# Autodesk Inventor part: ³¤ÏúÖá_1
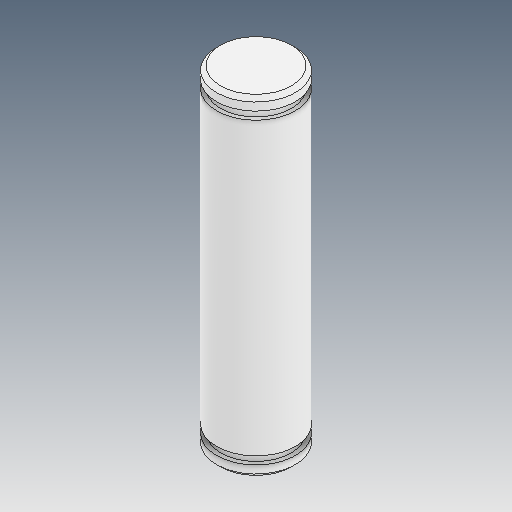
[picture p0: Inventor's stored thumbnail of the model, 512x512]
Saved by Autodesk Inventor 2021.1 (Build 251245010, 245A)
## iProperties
Created: 2021-05
Part Number: ³¤ÏúÖá_1
Material: Ogólny
Document SubType Name: Modeling
Designer: user
Density: 1 g/cm^3
Appearance: Domyślna
Author: user
Revision Number: ÈÎºÎ
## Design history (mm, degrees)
feature "ÊäÈë1"
node "Bryła1"
